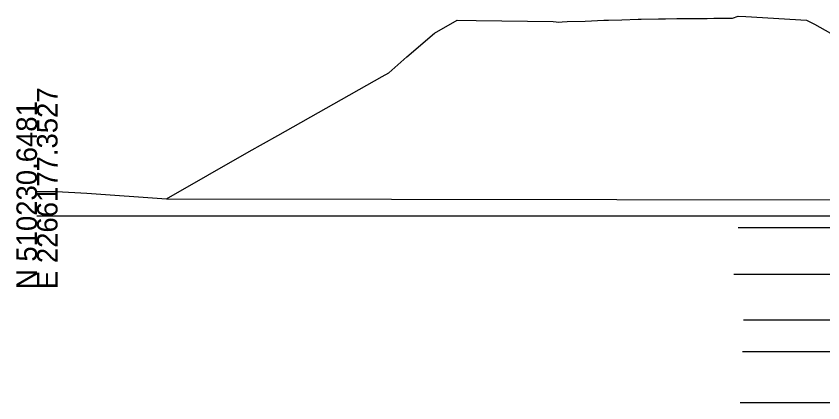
# Model space of a CAD drawing. Extents: x -827 to 2303, y -169 to 9934.
# Drawn here: x -2.8 to 107.1, y 8474.5 to 8527.2 of the extents above; entities that cross this region are included whole.
import ezdxf

# ---------------------------------------------------------------- set-up
doc = ezdxf.new("R2010")
doc.units = 0
for name, color, linetype in [('Default', 7, 'Continuous'), ('Exist Cross Section Cell', 7, 'Continuous'), ('Exist XS Ground Line', 7, 'Continuous'), ('Prop Road Sect_ Material - Contact (General - Major)', 7, 'Continuous'), ('Prop Road Sect_ Material - Contact (General - Minor)', 7, 'Continuous')]:
    doc.layers.add(name, color=color, linetype=linetype)

msp = doc.modelspace()

# ---------------------------------------------------------------- linework, layer by layer
at = {"layer": 'Exist Cross Section Cell'}
msp.add_line((0, 8500), (150, 8500), dxfattribs=at)
at = {"layer": 'Exist XS Ground Line'}
msp.add_lwpolyline([(0, 8503.36), (2.68, 8503.32), (6.81, 8503.05), (17.63, 8502.3), (28.91, 8508.74), (32.8, 8510.91), (47.04, 8518.97), (47.92, 8519.48), (50.4, 8521.63), (54.18, 8524.88), (57.26, 8526.63), (59.83, 8526.59), (70.33, 8526.46), (70.74, 8526.41), (71.06, 8526.37), (71.56, 8526.4), (72.25, 8526.44), (74.67, 8526.49), (77.24, 8526.64), (77.85, 8526.66), (79.71, 8526.69), (81.92, 8526.78), (82.34, 8526.8), (84.7, 8526.83), (85.64, 8526.84), (87.18, 8526.87), (87.61, 8526.87), (88.11, 8526.88), (88.8, 8526.88), (89.7, 8526.88), (90.56, 8526.89), (90.88, 8526.89), (91.32, 8526.89), (92.21, 8526.91), (93.6, 8526.92), (94.39, 8526.92), (94.75, 8526.91), (95.55, 8527.19), (96.59, 8527.13), (104.83, 8526.62), (105.92, 8526.09), (108.84, 8524.44)], dxfattribs=at)
at = {"layer": 'Prop Road Sect_ Material - Contact (General - Major)'}
msp.add_line((17.63, 8502.3), (238.52, 8501.92), dxfattribs=at)
at = {"layer": 'Prop Road Sect_ Material - Contact (General - Minor)'}
for p, q in [((95.53, 8498.4), (286.29, 8498.4)), ((286.82, 8492), (94.96, 8492)), ((96.26, 8485.8), (286, 8485.8)), ((96.14, 8481.5), (286.66, 8481.5)), ((286.77, 8474.5), (95.8, 8474.5))]:
    msp.add_line(p, q, dxfattribs=at)

# ---------------------------------------------------------------- texts
at = {"layer": 'Default'}
msp.add_text('-', height=0.0001, dxfattribs=at).set_placement((0, 8500))
msp.add_text('-', height=0.0001, dxfattribs=at).set_placement((0, 8500))
at = {"layer": 'Exist Cross Section Cell'}
for s, p in [('E 2266177.3527', (2.8, 8490)), ('N 510230.6481', (0, 8490))]:
    msp.add_text(s, height=2.8, rotation=90, dxfattribs=at).set_placement(p)

doc.saveas('drawing.dxf')
